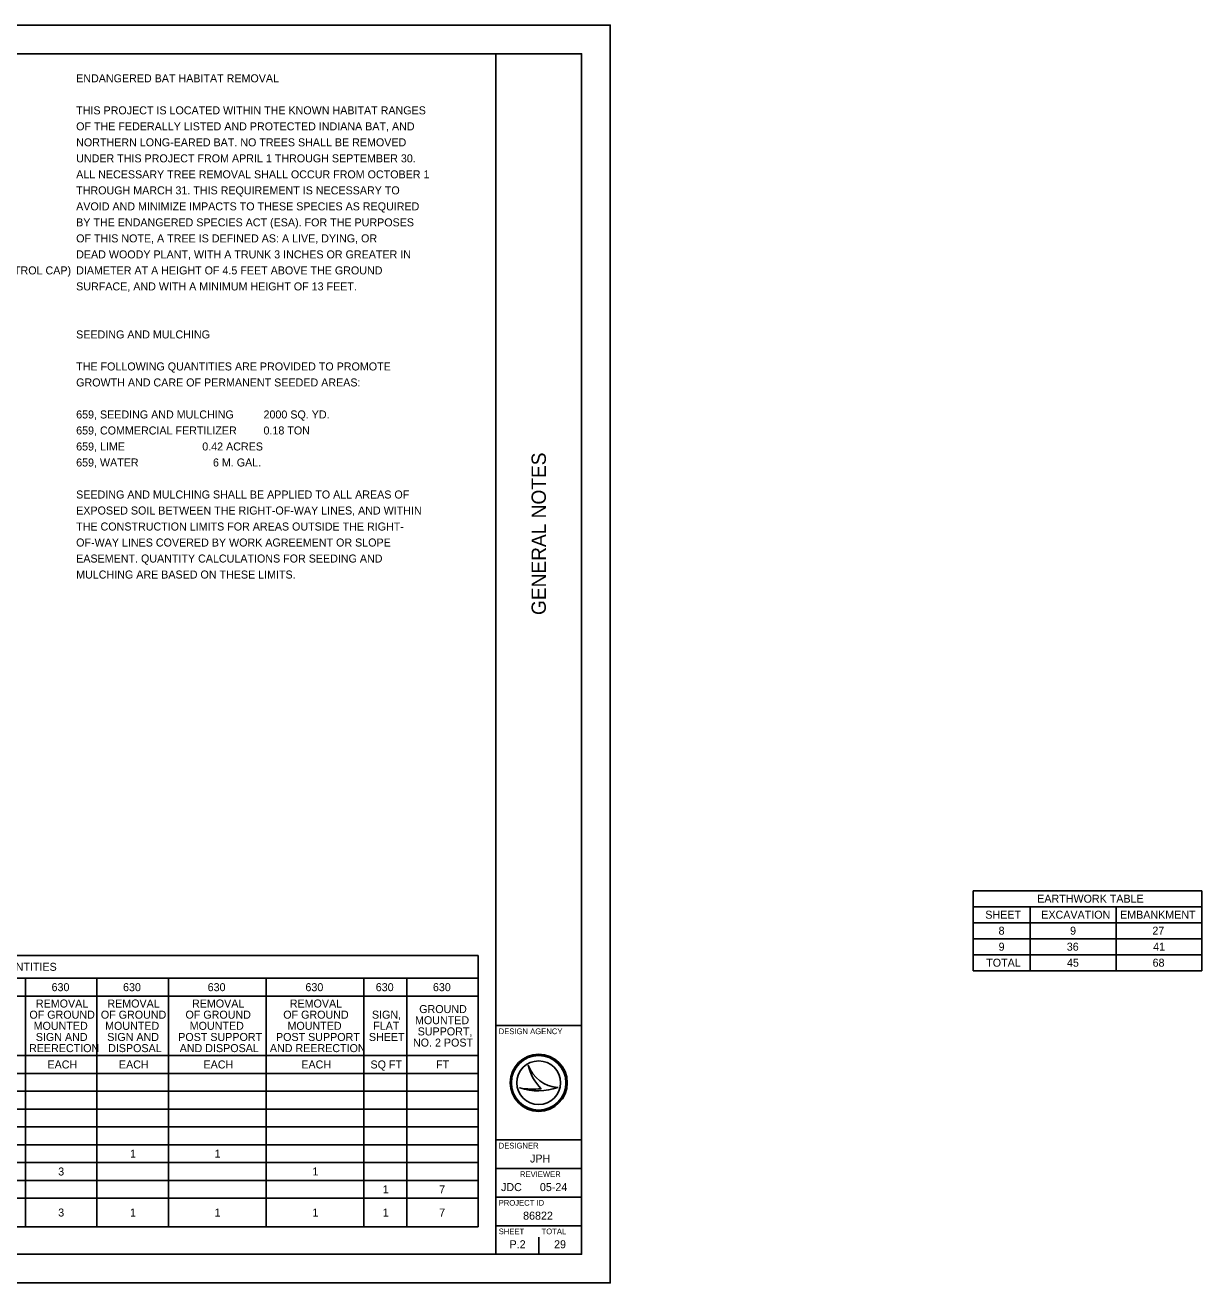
# Model space of a CAD drawing. Extents: x -42.4 to 44.3, y -21.7 to 22.
# Drawn here: x 23.77 to 44.35, y 0 to 22 of the extents above; entities that cross this region are included whole.
import ezdxf

# ---------------------------------------------------------------- set-up
doc = ezdxf.new("R2010")
doc.units = 0
for name, color, linetype in [('SH_Border', 7, 'Continuous'), ('SH_Cut_Line', 7, 'Continuous'), ('SH_Data', 7, 'Continuous'), ('SH_Text', 7, 'Continuous'), ('TX_P_1', 7, 'Continuous'), ('TX_P_20', 7, 'Continuous')]:
    doc.layers.add(name, color=color, linetype=linetype)

msp = doc.modelspace()

# ---------------------------------------------------------------- linework, layer by layer
at = {"layer": 'SH_Border'}
for p, q in [((32, 0.5), (32, 21.5)), ((32, 4.5), (33.5, 4.5)), ((32, 2.5), (33.5, 2.5)), ((32, 2), (33.5, 2)), ((32, 1.5), (33.5, 1.5)), ((32, 1), (33.5, 1))]:
    msp.add_line(p, q, dxfattribs=at)
msp.add_lwpolyline([(1.5, 21.5), (33.5, 21.5), (33.5, 0.5), (1.5, 0.5)], close=True, dxfattribs=at)
at = {"layer": 'SH_Cut_Line'}
msp.add_lwpolyline([(0, 0), (34, 0), (34, 22), (0, 22)], close=True, dxfattribs=at)
at = {"layer": 'SH_Data'}
for p, q in [((31.693, 5.728), (14.812, 5.728)), ((31.693, 0.98), (31.693, 5.728)), ((31.693, 5.328), (14.812, 5.328)), ((23.773, 0.98), (23.773, 5.328)), ((25.023, 0.98), (25.023, 5.328)), ((26.273, 0.98), (26.273, 5.328)), ((27.983, 0.98), (27.983, 5.328)), ((29.693, 0.98), (29.693, 5.328)), ((30.443, 0.98), (30.443, 5.328)), ((31.693, 5.016), (18.363, 5.016)), ((31.693, 0.98), (31.693, 5.016)), ((31.693, 3.976), (18.363, 3.976)), ((32.567, 3.81), (32.567, 3.81)), ((31.693, 3.664), (14.812, 3.664)), ((31.693, 3.352), (14.812, 3.352)), ((32.417, 3.41), (32.417, 3.41)), ((32.75, 3.5), (32.75, 3.5)), ((33.087, 3.419), (33.087, 3.419)), ((31.693, 3.04), (14.812, 3.04)), ((31.693, 2.728), (14.812, 2.728)), ((31.693, 2.416), (14.812, 2.416)), ((31.693, 2.104), (14.812, 2.104)), ((31.693, 1.792), (14.812, 1.792)), ((31.693, 1.48), (14.812, 1.48)), ((31.693, 1.48), (14.812, 1.48)), ((31.693, 0.98), (14.812, 0.98)), ((32.375, 0.675), (32.375, 0.675)), ((32.75, 0.5), (32.75, 0.8))]:
    msp.add_line(p, q, dxfattribs=at)
for radius in [0.5, 0.477, 0.477, 0.382]:
    msp.add_circle((32.75, 3.5), radius, dxfattribs=at)
for centre, radius, start, end in [((33.116, 3.998), 0.58, 198.9257, 198.9319), ((33.347, 3.97), 0.796, 191.6379, 191.6421), ((33.116, 3.998), 0.58, 198.9319, 267.1657), ((33.347, 3.97), 0.796, 191.6421, 226.0947), ((32.739, 4.37), 1.013, 251.4576, 290.0832), ((32.648, 4.654), 1.266, 259.4964, 259.4995), ((32.739, 4.37), 1.013, 251.4527, 251.4576), ((32.648, 4.654), 1.266, 259.4995, 276.6672)]:
    msp.add_arc(centre, radius, start, end, dxfattribs=at)
at = {"layer": 'TX_P_1'}
for p, q in [((40.348, 6.86), (44.348, 6.86)), ((40.348, 6.86), (40.348, 5.46)), ((44.348, 6.86), (44.348, 5.46)), ((40.348, 6.58), (44.348, 6.58)), ((41.348, 6.58), (41.348, 5.46)), ((42.848, 6.58), (42.848, 5.46)), ((40.348, 6.3), (44.348, 6.3)), ((40.348, 6.02), (44.348, 6.02)), ((40.348, 5.74), (44.348, 5.74)), ((40.348, 5.46), (44.348, 5.46))]:
    msp.add_line(p, q, dxfattribs=at)

# ---------------------------------------------------------------- texts
at = {"layer": 'SH_Data'}
msp.add_text('GENERAL NOTES', height=0.25, rotation=90, dxfattribs=at).set_placement((32.875, 11.682))
for s, height, p in [('ROADWAY ESTIMATED QUANTITIES', 0.14, (21.054, 5.458)), ('DESIGN AGENCY', 0.1, (32.05, 4.35)), ('DESIGNER', 0.1, (32.05, 2.35)), ('JPH', 0.14, (32.598, 2.105)), ('REVIEWER', 0.1, (32.422, 1.85)), ('JDC', 0.14, (32.091, 1.605)), ('05-24', 0.14, (32.771, 1.605)), ('PROJECT ID', 0.1, (32.05, 1.35)), ('86822', 0.14, (32.477, 1.105)), ('SHEET', 0.1, (32.05, 0.85)), ('TOTAL', 0.1, (32.8, 0.85)), ('P.2', 0.14, (32.24, 0.605)), ('29', 0.14, (33.019, 0.605))]:
    msp.add_text(s, height=height, dxfattribs=at).set_placement(p)
at = {"layer": 'SH_Text'}
for s, p in [('ENDANGERED BAT HABITAT REMOVAL', (24.66, 21)), ('THIS PROJECT IS LOCATED WITHIN THE KNOWN HABITAT RANGES', (24.66, 20.44)), ('OF THE FEDERALLY LISTED AND PROTECTED INDIANA BAT, AND', (24.66, 20.16)), ('NORTHERN LONG-EARED BAT. NO TREES SHALL BE REMOVED', (24.66, 19.88)), ('UNDER THIS PROJECT FROM APRIL 1 THROUGH SEPTEMBER 30.', (24.66, 19.6)), ('ALL NECESSARY TREE REMOVAL SHALL OCCUR FROM OCTOBER 1', (24.66, 19.32)), ('THROUGH MARCH 31. THIS REQUIREMENT IS NECESSARY TO', (24.66, 19.04)), ('AVOID AND MINIMIZE IMPACTS TO THESE SPECIES AS REQUIRED', (24.66, 18.76)), ('BY THE ENDANGERED SPECIES ACT (ESA). FOR THE PURPOSES', (24.66, 18.48)), ('OF THIS NOTE, A TREE IS DEFINED AS: A LIVE, DYING, OR', (24.66, 18.2)), ('DEAD WOODY PLANT, WITH A TRUNK 3 INCHES OR GREATER IN', (24.66, 17.92)), ('MONUMENT TYPE:  B (3/4" X 30" REBAR WITH ODOT DISTRICT 10 CONTROL CAP)', (17.24, 17.64)), ('DIAMETER AT A HEIGHT OF 4.5 FEET ABOVE THE GROUND', (24.66, 17.64)), ('SURFACE, AND WITH A MINIMUM HEIGHT OF 13 FEET.', (24.66, 17.36)), ('SEEDING AND MULCHING', (24.66, 16.52)), ('THE FOLLOWING QUANTITIES ARE PROVIDED TO PROMOTE', (24.66, 15.96)), ('GROWTH AND CARE OF PERMANENT SEEDED AREAS:', (24.66, 15.68)), ('659, SEEDING AND MULCHING          2000 SQ. YD.', (24.66, 15.12)), ('659, COMMERCIAL FERTILIZER         0.18 TON', (24.66, 14.84)), ('659, LIME                          0.42 ACRES', (24.66, 14.56)), ('659, WATER                         6 M. GAL.', (24.66, 14.28)), ('SEEDING AND MULCHING SHALL BE APPLIED TO ALL AREAS OF', (24.66, 13.72)), ('EXPOSED SOIL BETWEEN THE RIGHT-OF-WAY LINES, AND WITHIN', (24.66, 13.44)), ('THE CONSTRUCTION LIMITS FOR AREAS OUTSIDE THE RIGHT-', (24.66, 13.16)), ('OF-WAY LINES COVERED BY WORK AGREEMENT OR SLOPE', (24.66, 12.88)), ('EASEMENT. QUANTITY CALCULATIONS FOR SEEDING AND', (24.66, 12.6)), ('MULCHING ARE BASED ON THESE LIMITS.', (24.66, 12.32))]:
    msp.add_text(s, height=0.14, dxfattribs=at).set_placement(p)
at = {"layer": 'TX_P_1'}
for s, p in [('EARTHWORK TABLE', (41.469, 6.65)), ('SHEET', (40.561, 6.37)), ('EXCAVATION', (41.54, 6.37)), ('EMBANKMENT', (42.918, 6.37)), ('8', (40.793, 6.09)), ('9', (42.044, 6.09)), ('27', (43.483, 6.09)), ('9', (40.794, 5.81)), ('36', (41.986, 5.81)), ('41', (43.497, 5.81)), ('TOTAL', (40.577, 5.53)), ('45', (41.989, 5.53)), ('68', (43.487, 5.53))]:
    msp.add_text(s, height=0.14, dxfattribs=at).set_placement(p)
at = {"layer": 'TX_P_20'}
for s, p in [('630', (24.23, 5.102)), ('630', (25.48, 5.102)), ('630', (26.96, 5.102)), ('630', (28.67, 5.102)), ('630', (29.9, 5.102)), ('630', (30.9, 5.102)), ('REMOVAL', (23.956, 4.816)), ('REMOVAL', (25.206, 4.816)), ('REMOVAL', (26.686, 4.816)), ('REMOVAL', (28.396, 4.816)), ('GROUND', (30.66, 4.719)), ('OF GROUND', (23.842, 4.621)), ('OF GROUND', (25.092, 4.621)), ('OF GROUND', (26.572, 4.621)), ('OF GROUND', (28.282, 4.621)), ('SIGN,', (29.833, 4.621)), ('MOUNTED', (30.586, 4.524)), ('MOUNTED', (23.916, 4.426)), ('MOUNTED', (25.166, 4.426)), ('MOUNTED', (26.646, 4.426)), ('MOUNTED', (28.356, 4.426)), ('FLAT', (29.855, 4.426)), ('SUPPORT,', (30.633, 4.328)), ('SIGN AND', (23.954, 4.231)), ('SIGN AND', (25.204, 4.231)), ('POST SUPPORT', (26.445, 4.231)), ('POST SUPPORT', (28.155, 4.231)), ('SHEET', (29.78, 4.231)), ('NO. 2 POST', (30.551, 4.133)), ('REERECTION', (23.836, 4.036)), ('DISPOSAL', (25.219, 4.036)), ('AND DISPOSAL', (26.471, 4.036)), ('AND REERECTION', (28.048, 4.036)), ('EACH', (24.158, 3.75)), ('EACH', (25.408, 3.75)), ('EACH', (26.888, 3.75)), ('EACH', (28.598, 3.75)), ('SQ FT', (29.808, 3.75)), ('FT', (30.956, 3.75)), ('1', (25.602, 2.19)), ('1', (27.082, 2.19)), ('3', (24.346, 1.878)), ('1', (28.792, 1.878)), ('1', (30.022, 1.566)), ('7', (31.009, 1.566)), ('3', (24.346, 1.16)), ('1', (25.602, 1.16)), ('1', (27.082, 1.16)), ('1', (28.792, 1.16)), ('1', (30.022, 1.16)), ('7', (31.009, 1.16))]:
    msp.add_text(s, height=0.14, dxfattribs=at).set_placement(p)

doc.saveas('drawing.dxf')
